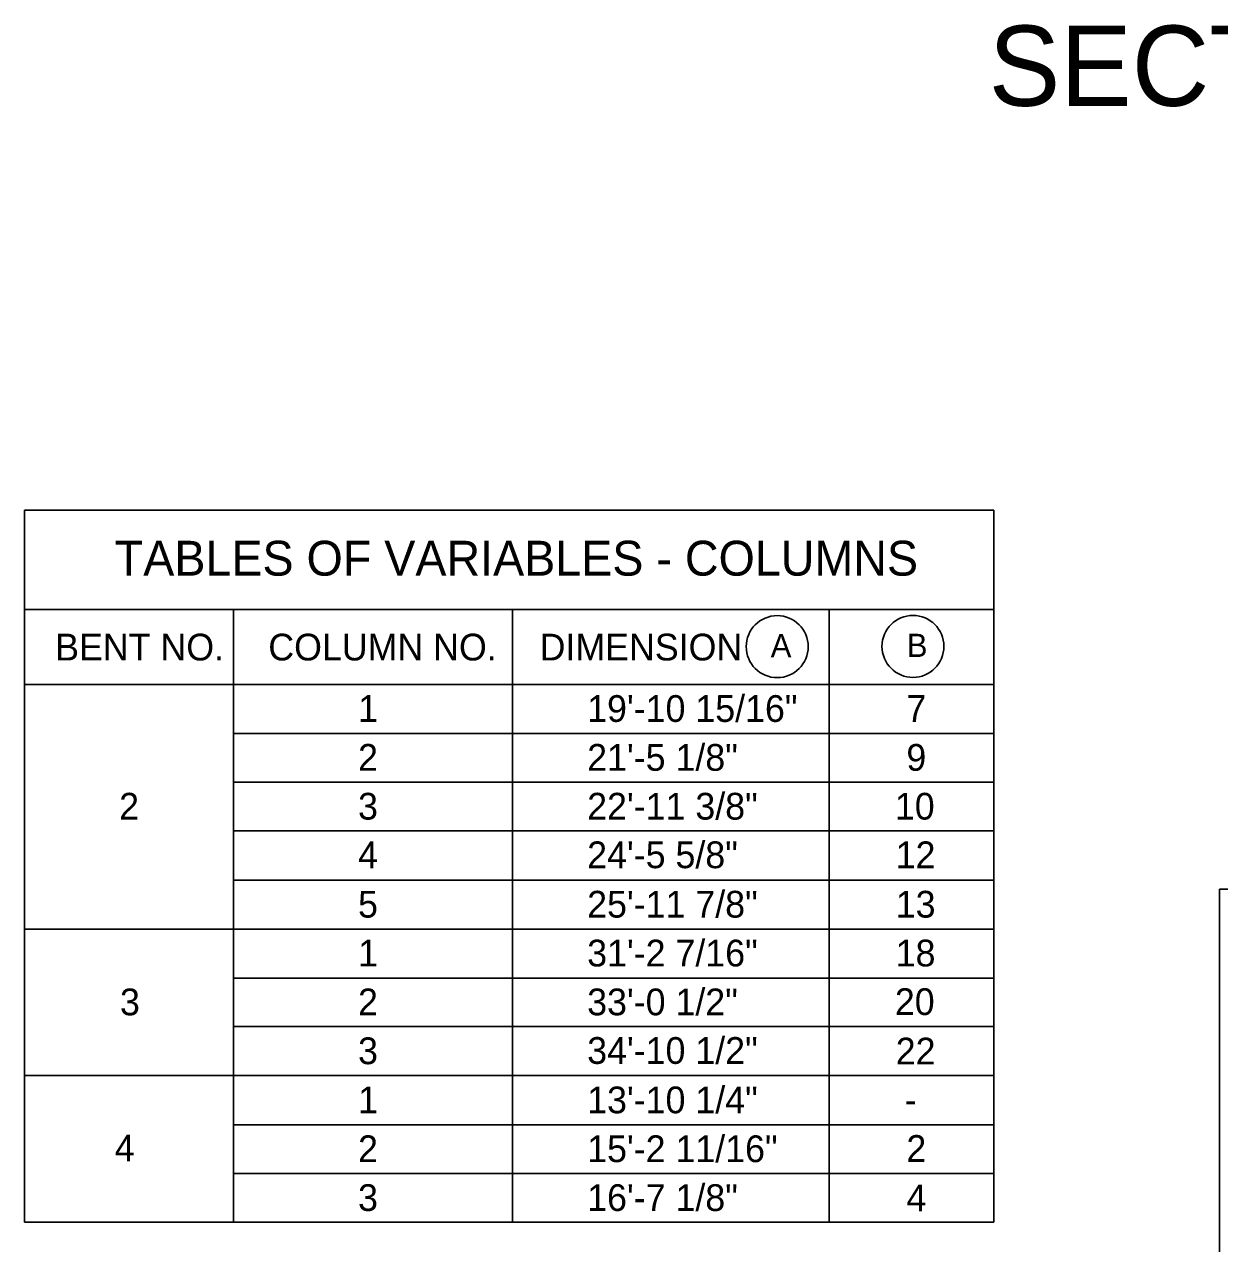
# Model space of a CAD drawing. Extents: x 1970675.2 to 1970711.3, y 796145.2 to 796167.2.
# Drawn here: x 1970699.73 to 1970705.32, y 796149.37 to 796155.06 of the extents above; entities that cross this region are included whole.
import ezdxf

# ---------------------------------------------------------------- set-up
doc = ezdxf.new("R2010")
doc.units = 0
for name, color, linetype in [('BR_AUTO DIMENSION', 7, 'Continuous'), ('BR_BORDER LINES', 7, 'Continuous'), ('BR_TABLE LINES', 7, 'Continuous'), ('BR_TEXT', 7, 'Continuous')]:
    doc.layers.add(name, color=color, linetype=linetype)

msp = doc.modelspace()

# ---------------------------------------------------------------- linework, layer by layer
at = {"layer": 'BR_AUTO DIMENSION'}
for centre in [(1970703.2506, 796152.1564), (1970703.8852, 796152.1575)]:
    msp.add_circle(centre, 0.1449, dxfattribs=at)
at = {"layer": 'BR_BORDER LINES'}
for p, q in [((1970705.3189, 796145.7463), (1970705.3189, 796151.0229)), ((1970705.3189, 796151.0229), (1970710.7358, 796151.0229))]:
    msp.add_line(p, q, dxfattribs=at)
at = {"layer": 'BR_TABLE LINES'}
for p, q in [((1970699.7306, 796152.794), (1970704.263, 796152.794)), ((1970699.7306, 796149.4665), (1970699.7306, 796152.794)), ((1970704.263, 796149.4665), (1970704.263, 796152.794)), ((1970699.7306, 796152.3292), (1970704.263, 796152.3292)), ((1970700.7089, 796149.4665), (1970700.7089, 796152.3292)), ((1970702.0132, 796149.4665), (1970702.0132, 796152.3292)), ((1970703.4942, 796149.4665), (1970703.4942, 796152.3292)), ((1970699.7306, 796151.9788), (1970704.263, 796151.9788)), ((1970700.7089, 796151.7506), (1970704.263, 796151.7506)), ((1970700.7089, 796151.5223), (1970704.263, 796151.5223)), ((1970700.7089, 796151.2953), (1970704.263, 796151.2953)), ((1970700.7089, 796151.0644), (1970704.263, 796151.0644)), ((1970699.7306, 796150.8362), (1970704.263, 796150.8362)), ((1970700.7089, 796150.6079), (1970704.263, 796150.6079)), ((1970700.7089, 796150.3809), (1970704.263, 796150.3809)), ((1970699.7306, 796150.1526), (1970704.263, 796150.1526)), ((1970700.7089, 796149.9218), (1970704.263, 796149.9218)), ((1970700.7089, 796149.6948), (1970704.263, 796149.6948)), ((1970699.7306, 796149.4665), (1970704.263, 796149.4665))]:
    msp.add_line(p, q, dxfattribs=at)

# ---------------------------------------------------------------- texts
at = {"layer": 'BR_TEXT'}
for s, height, p in [('SECTION A-A', 0.374999, (1970704.2393, 796154.6833)), ('TABLES OF VARIABLES - COLUMNS', 0.163046, (1970700.1532, 796152.488)), ('BENT NO.', 0.125, (1970699.8747, 796152.0918)), ('COLUMN NO.', 0.125, (1970700.8711, 796152.0918)), ('DIMENSION', 0.125, (1970702.1397, 796152.0918)), ('A', 0.1087, (1970703.2199, 796152.1068)), ('B', 0.1087, (1970703.8562, 796152.1079)), ('1', 0.125, (1970701.2908, 796151.8046)), ('19\'-10 15/16"', 0.125002, (1970702.362, 796151.8046)), ('7', 0.125, (1970703.8545, 796151.8046)), ('2', 0.125, (1970701.2908, 796151.5763)), ('21\'-5 1/8"', 0.125, (1970702.362, 796151.5763)), ('9', 0.125, (1970703.8545, 796151.5763)), ('2', 0.125, (1970700.1738, 796151.3481)), ('3', 0.125, (1970701.2908, 796151.3481)), ('22\'-11 3/8"', 0.125002, (1970702.362, 796151.3481)), ('10', 0.125, (1970703.8007, 796151.3481)), ('4', 0.125, (1970701.2908, 796151.1211)), ('24\'-5 5/8"', 0.125, (1970702.362, 796151.1211)), ('12', 0.125, (1970703.8045, 796151.1211)), ('5', 0.125, (1970701.2908, 796150.8902)), ('25\'-11 7/8"', 0.125002, (1970702.362, 796150.8902)), ('13', 0.125, (1970703.8048, 796150.8902)), ('1', 0.125, (1970701.2908, 796150.6619)), ('31\'-2 7/16"', 0.125002, (1970702.362, 796150.662)), ('18', 0.125, (1970703.8045, 796150.662)), ('3', 0.125, (1970700.1777, 796150.4337)), ('2', 0.125, (1970701.2908, 796150.4337)), ('33\'-0 1/2"', 0.125, (1970702.362, 796150.4337)), ('20', 0.125, (1970703.8007, 796150.4349)), ('3', 0.125, (1970701.2908, 796150.2054)), ('34\'-10 1/2"', 0.125002, (1970702.362, 796150.2067)), ('22', 0.125, (1970703.8048, 796150.2041)), ('1', 0.125, (1970701.2908, 796149.9758)), ('13\'-10 1/4"', 0.125002, (1970702.362, 796149.9758)), ('-', 0.125, (1970703.8462, 796149.9758)), ('4', 0.125, (1970700.1532, 796149.7514)), ('2', 0.125, (1970701.2908, 796149.7476)), ('15\'-2 11/16"', 0.125002, (1970702.362, 796149.7476)), ('2', 0.125, (1970703.8545, 796149.7488)), ('3', 0.125, (1970701.2908, 796149.5193)), ('16\'-7 1/8"', 0.125, (1970702.362, 796149.5193)), ('4', 0.125, (1970703.8548, 796149.518))]:
    msp.add_text(s, height=height, dxfattribs=at).set_placement(p)

doc.saveas('drawing.dxf')
